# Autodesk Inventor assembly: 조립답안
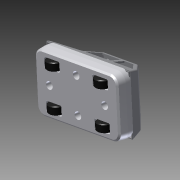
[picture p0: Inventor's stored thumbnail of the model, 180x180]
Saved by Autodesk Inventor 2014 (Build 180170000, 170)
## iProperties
Created: 2015-05
Part Number: 조립답안
Document SubType Name: Assembly
Designer: Administrator
Author: Administrator
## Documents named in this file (5)
- C:\Users\Administrator\Desktop\450508V1002\조립답안.iam
- C:\Users\Administrator\Desktop\450508V1002\커버.ipt
- C:\Users\Administrator\Desktop\450508V1002\바퀴고정부.ipt
- C:\Users\Administrator\Desktop\450508V1002\바퀴.ipt
- C:\Users\Administrator\Documents\본체.ipt
